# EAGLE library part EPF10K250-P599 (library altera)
EPF10K250 FLEX 10K family
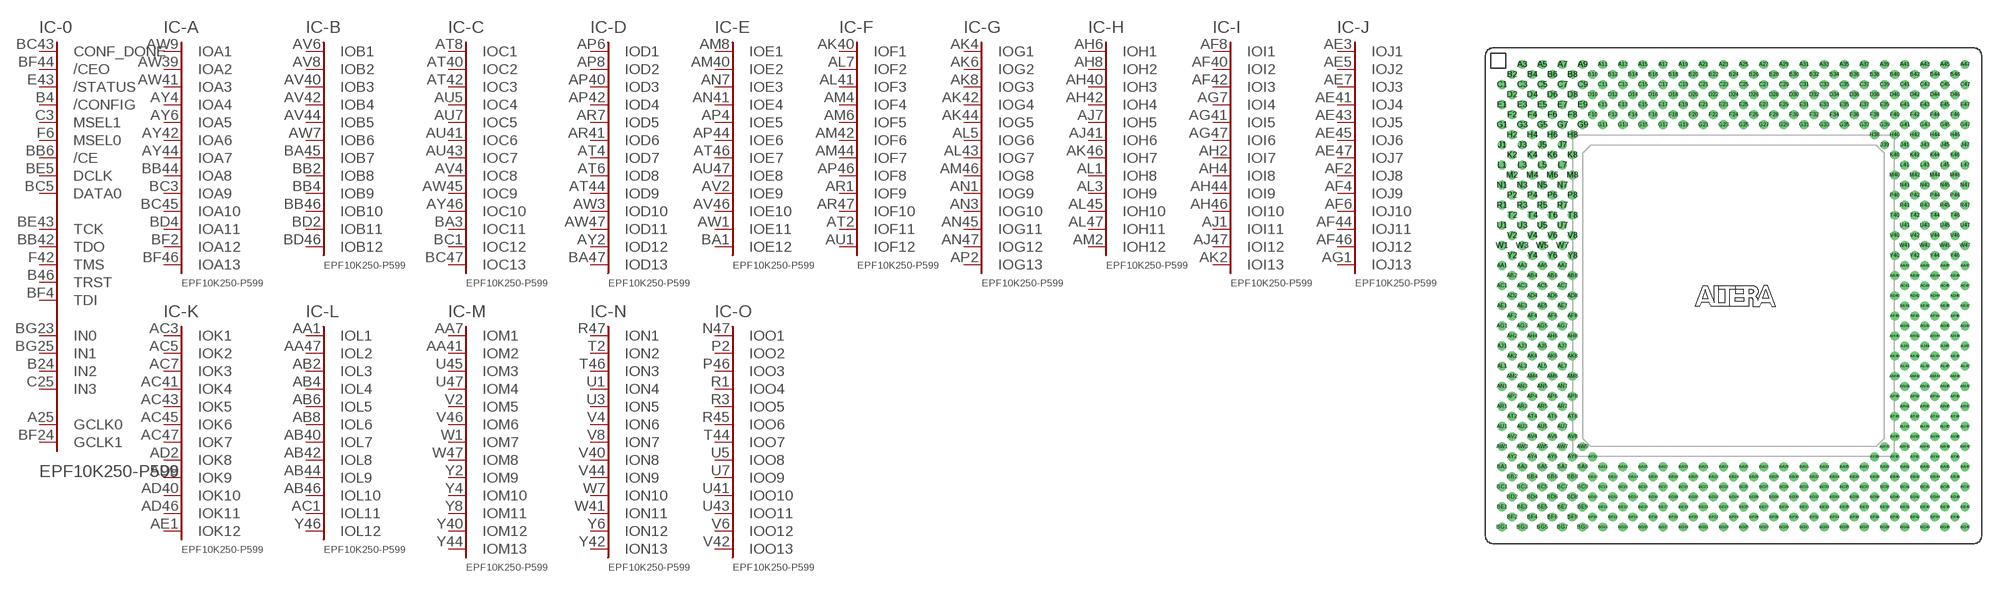
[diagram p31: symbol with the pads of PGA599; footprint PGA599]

Designator prefix IC; gates -0=K250_C -A=A13-250 -B=B12-250 -C=C13-250 -D=D13-250 -E=E12-250 -F=F12-250 -G=G13-250 -H=H12-250 -I=I13-250 -J=J13-250 -K=K12-250 -L=L12-250 -M=M13-250 -N=N13-250 -O=O13-250 -Q=Q14-250 -S=S13-250 -T=T14-250 -1=62-250 -2=122-250 -3=182-250 -4=242-250 -5=302-250 -6=361-250 -7=412-250 -8=471-250 -9=531-250 -10=583-250 -11=642-250 -12=702-250 -13=762-250 -P=P14-250 -R=R12-250 GI1=GNDINT GI2=GNDINT GI3=GNDINT GI4=GNDINT GI5=GNDINT GI6=GNDINT GI7=GNDINT GI8=GNDINT GI9=GNDINT GI10=GNDINT GI11=GNDINT GI12=GNDINT GI13=GNDINT GI14=GNDINT GI15=GNDINT GI16=GNDINT GI17=GNDINT GI18=GNDINT GI19=GNDINT GI20=GNDINT GI21=GNDINT GI22=GNDINT GI23=GNDINT GI24=GNDINT GI25=GNDINT GI26=GNDINT GO1=GNDIO GO2=GNDIO GO3=GNDIO GO4=GNDIO GO5=GNDIO GO6=GNDIO GO7=GNDIO GO8=GNDIO GO9=GNDIO GO10=GNDIO GO11=GNDIO GO12=GNDIO GO13=GNDIO GO14=GNDIO GO15=GNDIO GO16=GNDIO GO17=GNDIO GO18=GNDIO GO19=GNDIO GO20=GNDIO GO21=GNDIO GO22=GNDIO GO23=GNDIO GO24=GNDIO GO25=GNDIO GO26=GNDIO GO27=GNDIO GO28=GNDIO GO29=GNDIO GO30=GNDIO GO31=GNDIO V1=VCCINT V2=VCCINT V3=VCCINT V4=VCCINT V5=VCCINT V6=VCCINT V7=VCCINT V8=VCCINT V9=VCCINT V10=VCCINT V11=VCCINT V12=VCCINT V13=VCCINT V14=VCCINT V15=VCCINT V16=VCCINT V17=VCCINT V18=VCCINT V19=VCCINT V20=VCCINT V21=VCCINT V22=VCCINT V23=VCCINT V24=VCCINT V25=VCCINT V26=VCCINT VO1=VCCIO VO2=VCCIO VO3=VCCIO VO4=VCCIO VO5=VCCIO VO6=VCCIO VO7=VCCIO VO8=VCCIO VO9=VCCIO VO10=VCCIO VO11=VCCIO VO12=VCCIO VO13=VCCIO VO14=VCCIO VO15=VCCIO VO16=VCCIO VO17=VCCIO VO18=VCCIO VO19=VCCIO VO20=VCCIO VO21=VCCIO VO22=VCCIO VO23=VCCIO VO24=VCCIO VO25=VCCIO VO26=VCCIO VO27=VCCIO VO28=VCCIO VO29=VCCIO VO30=VCCIO VO31=VCCIO VO32=VCCIO

## EPF10K250-P599 (OC_FARNELL: unknown; OC_NEWARK: unknown)  [PGA599]
A3  V5:VCC  pwr
A5  -2:IO71
A7  -2:IO111
A9  -3:IO151
A11  -3:IO171
A13  -4:IO191
A15  -4:IO231
A17  -5:IO291
A19  -6:IO311
A21  -6:IO331
A23  -7:IO381
A25  -0:GCLK0  in
A27  -7:IO401
A29  -8:IO441
A31  -8:IO471
A33  -9:IO511
A35  -10:IO551
A37  -10:IO581
A39  -11:IO591
A41  -11:IO621
A43  -12:IO691
A45  V6:VCC  pwr
A47  GI7:GND  pwr
AA1  -L:IOL1
AA3  GI1:GND  pwr
AA5  VO1:VCCIO  pwr
AA7  -M:IOM1
AA41  -M:IOM2
AA43  VO2:VCCIO  pwr
AA45  GI2:GND  pwr
AA47  -L:IOL2
AB2  -L:IOL3
AB4  -L:IOL4
AB6  -L:IOL5
AB8  -L:IOL6
AB40  -L:IOL7
AB42  -L:IOL8
AB44  -L:IOL9
AB46  -L:IOL10
AC1  -L:IOL11
AC3  -K:IOK1
AC5  -K:IOK2
AC7  -K:IOK3
AC41  -K:IOK4
AC43  -K:IOK5
AC45  -K:IOK6
AC47  -K:IOK7
AD2  -K:IOK8
AD4  VO3:VCCIO  pwr
AD6  GO1:GNDIO  pwr
AD8  -K:IOK9
AD40  -K:IOK10
AD42  GO2:GNDIO  pwr
AD44  VO4:VCCIO  pwr
AD46  -K:IOK11
AE1  -K:IOK12
AE3  -J:IOJ1
AE5  -J:IOJ2
AE7  -J:IOJ3
AE41  -J:IOJ4
AE43  -J:IOJ5
AE45  -J:IOJ6
AE47  -J:IOJ7
AF2  -J:IOJ8
AF4  -J:IOJ9
AF6  -J:IOJ10
AF8  -I:IOI1
AF40  -I:IOI2
AF42  -I:IOI3
AF44  -J:IOJ11
AF46  -J:IOJ12
AG1  -J:IOJ13
AG3  GI3:GND  pwr
AG5  VO5:VCCIO  pwr
AG7  -I:IOI4
AG41  -I:IOI5
AG43  VO6:VCCIO  pwr
AG45  GI4:GND  pwr
AG47  -I:IOI6
AH2  -I:IOI7
AH4  -I:IOI8
AH6  -H:IOH1
AH8  -H:IOH2
AH40  -H:IOH3
AH42  -H:IOH4
AH44  -I:IOI9
AH46  -I:IOI10
AJ1  -I:IOI11
AJ3  V1:VCC  pwr
AJ5  GO3:GNDIO  pwr
AJ7  -H:IOH5
AJ41  -H:IOH6
AJ43  GO4:GNDIO  pwr
AJ45  V2:VCC  pwr
AJ47  -I:IOI12
AK2  -I:IOI13
AK4  -G:IOG1
AK6  -G:IOG2
AK8  -G:IOG3
AK40  -F:IOF1
AK42  -G:IOG4
AK44  -G:IOG5
AK46  -H:IOH7
AL1  -H:IOH8
AL3  -H:IOH9
AL5  -G:IOG6
AL7  -F:IOF2
AL41  -F:IOF3
AL43  -G:IOG7
AL45  -H:IOH10
AL47  -H:IOH11
AM2  -H:IOH12
AM4  -F:IOF4
AM6  -F:IOF5
AM8  -E:IOE1
AM40  -E:IOE2
AM42  -F:IOF6
AM44  -F:IOF7
AM46  -G:IOG8
AN1  -G:IOG9
AN3  -G:IOG10
AN5  VO7:VCCIO  pwr
AN7  -E:IOE3
AN41  -E:IOE4
AN43  VO8:VCCIO  pwr
AN45  -G:IOG11
AN47  -G:IOG12
AP2  -G:IOG13
AP4  -E:IOE5
AP6  -D:IOD1
AP8  -D:IOD2
AP40  -D:IOD3
AP42  -D:IOD4
AP44  -E:IOE6
AP46  -F:IOF8
AR1  -F:IOF9
AR3  GI5:GND  pwr
AR5  GO5:GNDIO  pwr
AR7  -D:IOD5
AR41  -D:IOD6
AR43  GO6:GNDIO  pwr
AR45  GI6:GND  pwr
AR47  -F:IOF10
AT2  -F:IOF11
AT4  -D:IOD7
AT6  -D:IOD8
AT8  -C:IOC1
AT40  -C:IOC2
AT42  -C:IOC3
AT44  -D:IOD9
AT46  -E:IOE7
AU1  -F:IOF12
AU3  V3:VCC  pwr
AU5  -C:IOC4
AU7  -C:IOC5
AU41  -C:IOC6
AU43  -C:IOC7
AU45  V4:VCC  pwr
AU47  -E:IOE8
AV2  -E:IOE9
AV4  -C:IOC8
AV6  -B:IOB1
AV8  -B:IOB2
AV40  -B:IOB3
AV42  -B:IOB4
AV44  -B:IOB5
AV46  -E:IOE10
AW1  -E:IOE11
AW3  -D:IOD10
AW5  VO9:VCCIO  pwr
AW7  -B:IOB6
AW9  -A:IOA1
AW39  -A:IOA2
AW41  -A:IOA3
AW43  VO10:VCCIO  pwr
AW45  -C:IOC9
AW47  -D:IOD11
AY2  -D:IOD12
AY4  -A:IOA4
AY6  -A:IOA5
AY8  GO7:GNDIO  pwr
AY10  -1:IO11
AY38  -13:IO761
AY40  GO8:GNDIO  pwr
AY42  -A:IOA6
AY44  -A:IOA7
AY46  -C:IOC10
B2  GI17:GND  pwr
B4  -0:/CONFIG  in
B6  -1:IO32
B8  -2:IO103
B10  -3:IO143
B12  -3:IO182
B14  -4:IO212
B16  -5:IO263
B18  -5:IO302
B20  -6:IO323
B22  -6:IO352
B24  -0:IN2  in
B26  -7:IO392
B28  -8:IO432
B30  -8:IO452
B32  -9:IO492
B34  -10:IO543
B36  -10:IO572
B38  -11:IO612
B40  -11:IO632
B42  -12:IO702
B44  -13:IO743
B46  -0:TRST
BA1  -E:IOE12
BA3  -C:IOC11
BA5  GO9:GNDIO  pwr
BA7  VO11:VCCIO  pwr
BA9  -1:IO21
BA11  -1:IO51
BA13  -2:IO101
BA15  -3:IO141
BA17  -4:IO211
BA19  -5:IO261
BA21  -6:IO332
BA23  -7:IO371
BA25  -7:IO402
BA27  -8:IO442
BA29  -9:IO512
BA31  -10:IO561
BA33  -11:IO622
BA35  -12:IO661
BA37  -13:IO721
BA39  -13:IO741
BA41  VO12:VCCIO  pwr
BA43  GO10:GNDIO  pwr
BA45  -B:IOB7
BA47  -D:IOD13
BB2  -B:IOB8
BB4  -B:IOB9
BB6  -0:/CE  in
BB8  -1:IO41
BB10  -2:IO81
BB12  -2:IO121
BB14  -3:IO161
BB16  -4:IO201
BB18  -5:IO251
BB20  -6:IO321
BB22  -6:IO361
BB24  GO11:GNDIO  pwr
BB26  -8:IO421
BB28  -8:IO461
BB30  -9:IO521
BB32  -10:IO582
BB34  -11:IO611
BB36  -12:IO651
BB38  -12:IO692
BB40  -13:IO731
BB42  -0:TDO
BB44  -A:IOA8
BB46  -B:IOB10
BC1  -C:IOC12
BC3  -A:IOA9
BC5  -0:DATA0  in
BC7  GO12:GNDIO  pwr
BC9  VO13:VCCIO  pwr
BC11  -2:IO91
BC13  GO13:GNDIO  pwr
BC15  VO14:VCCIO  pwr
BC17  -5:IO281
BC19  GO14:GNDIO  pwr
BC21  VO15:VCCIO  pwr
BC23  -7:IO382
BC25  -7:IO403
BC27  VO16:VCCIO  pwr
BC29  GO15:GNDIO  pwr
BC31  -9:IO501
BC33  VO17:VCCIO  pwr
BC35  GO16:GNDIO  pwr
BC37  -12:IO681
BC39  VO18:VCCIO  pwr
BC41  GO17:GNDIO  pwr
BC43  -0:CONF_DONE  in
BC45  -A:IOA10
BC47  -C:IOC13
BD2  -B:IOB11
BD4  -A:IOA11
BD6  -1:IO22
BD8  -1:IO42
BD10  -3:IO131
BD12  -3:IO172
BD14  -4:IO221
BD16  -4:IO241
BD18  -5:IO292
BD20  -6:IO341
BD22  -7:IO362
BD24  VO19:VCCIO  pwr
BD26  -7:IO411
BD28  -8:IO431
BD30  -9:IO481
BD32  -10:IO541
BD34  -10:IO552
BD36  -11:IO601
BD38  -11:IO641
BD40  -13:IO722
BD42  -13:IO751
BD44  GI8:GND  pwr
BD46  -B:IOB12
BE1  V7:VCC  pwr
BE3  GI9:GND  pwr
BE5  -0:DCLK  in
BE7  -1:IO61
BE9  -2:IO82
BE11  V8:VCC  pwr
BE13  GI10:GND  pwr
BE15  -4:IO222
BE17  -5:IO271
BE19  V9:VCC  pwr
BE21  GI11:GND  pwr
BE23  -7:IO383
BE25  -7:IO391
BE27  GI12:GND  pwr
BE29  V10:VCC  pwr
BE31  -9:IO502
BE33  -10:IO562
BE35  GI13:GND  pwr
BE37  V11:VCC  pwr
BE39  -12:IO682
BE41  -13:IO711
BE43  -0:TCK
BE45  GI14:GND  pwr
BE47  V12:VCC  pwr
BF2  -A:IOA12
BF4  -0:TDI
BF6  -1:IO31
BF8  -2:IO102
BF10  -3:IO142
BF12  -3:IO181
BF14  -4:IO202
BF16  -5:IO262
BF18  -5:IO301
BF20  -6:IO322
BF22  -6:IO351
BF24  -0:GCLK1  in
BF26  -8:IO422
BF28  -8:IO451
BF30  -9:IO482
BF32  -9:IO522
BF34  -10:IO571
BF36  -11:IO592
BF38  -11:IO631
BF40  -12:IO671
BF42  -13:IO742
BF44  -0:/CEO  in
BF46  -A:IOA13
BG1  GI15:GND  pwr
BG3  V13:VCC  pwr
BG5  -2:IO72
BG7  -2:IO112
BG9  -3:IO152
BG11  -3:IO162
BG13  -4:IO192
BG15  -4:IO232
BG17  -5:IO282
BG19  -6:IO312
BG21  -6:IO342
BG23  -0:IN0  in
BG25  -0:IN1  in
BG27  -8:IO443
BG29  -8:IO462
BG31  -9:IO491
BG33  -10:IO542
BG35  -10:IO583
BG37  -11:IO602
BG39  -11:IO623
BG41  -12:IO662
BG43  -12:IO701
BG45  V14:VCC  pwr
BG47  GI16:GND  pwr
C1  V15:VCC  pwr
C3  -0:MSEL1  in
C5  -1:IO23
C7  -1:IO62
C9  -2:IO92
C11  V16:VCC  pwr
C13  GI18:GND  pwr
C15  -4:IO223
C17  -5:IO272
C19  V17:VCC  pwr
C21  GI19:GND  pwr
C23  -7:IO372
C25  -0:IN3  in
C27  GI20:GND  pwr
C29  V18:VCC  pwr
C31  -9:IO483
C33  -9:IO523
C35  GI21:GND  pwr
C37  V19:VCC  pwr
C39  -12:IO672
C41  -13:IO732
C43  -13:IO752
C45  GI22:GND  pwr
C47  V20:VCC  pwr
D2  -T:IOT1
D4  GI23:GND  pwr
D6  -1:IO43
D8  -1:IO52
D10  -3:IO132
D12  -3:IO173
D14  -4:IO233
D16  -4:IO242
D18  -5:IO293
D20  -6:IO343
D22  -6:IO353
D24  VO20:VCCIO  pwr
D26  -8:IO423
D28  -8:IO433
D30  -9:IO493
D32  -9:IO531
D34  -10:IO553
D36  -11:IO603
D38  -11:IO642
D40  -12:IO683
D42  -13:IO723
D44  -T:IOT2
D46  -T:IOT3
E1  -T:IOT4
E3  -T:IOT5
E5  V21:VCC  pwr
E7  GO18:GNDIO  pwr
E9  VO21:VCCIO  pwr
E11  -2:IO93
E13  GO19:GNDIO  pwr
E15  VO22:VCCIO  pwr
E17  -5:IO283
E19  GO20:GNDIO  pwr
E21  VO23:VCCIO  pwr
E23  -7:IO373
E25  -7:IO393
E27  VO24:VCCIO  pwr
E29  GO21:GNDIO  pwr
E31  -9:IO503
E33  VO25:VCCIO  pwr
E35  GO22:GNDIO  pwr
E37  -12:IO652
E39  VO26:VCCIO  pwr
E41  GO23:GNDIO  pwr
E43  -0:/STATUS  in
E45  -T:IOT6
E47  -T:IOT7
F2  -S:IOS1
F4  -T:IOT8
F6  -0:MSEL0  in
F8  -1:IO33
F10  -2:IO83
F12  -2:IO122
F14  -3:IO163
F16  -4:IO203
F18  -5:IO252
F20  -6:IO313
F22  -7:IO363
F24  GO24:GNDIO  pwr
F26  -7:IO412
F28  -8:IO463
F30  -10:IO532
F32  -10:IO573
F34  -11:IO613
F36  -12:IO673
F38  -12:IO693
F40  -13:IO733
F42  -0:TMS
F44  -S:IOS2
F46  -S:IOS3
G1  -R:IOR1
G3  -S:IOS4
G5  GO25:GNDIO  pwr
G7  VO27:VCCIO  pwr
G9  -1:IO12
G11  -1:IO53
G13  -2:IO113
G15  -3:IO153
G17  -4:IO213
G19  -5:IO273
G21  -6:IO333
G23  GI24:GND  pwr
G25  V22:VCC  pwr
G27  -8:IO453
G29  -9:IO513
G31  -10:IO563
G33  -11:IO633
G35  -12:IO663
G37  -13:IO712
G39  -13:IO753
G41  VO28:VCCIO  pwr
G43  GO26:GNDIO  pwr
G45  -S:IOS5
G47  -R:IOR2
H2  -R:IOR3
H4  -S:IOS6
H6  -T:IOT9
H8  -T:IOT10
H38  -13:IO762
H40  GO27:GNDIO  pwr
H42  -T:IOT11
H44  -R:IOR4
H46  -Q:IOQ1
J1  -Q:IOQ2
J3  -Q:IOQ3
J5  VO29:VCCIO  pwr
J7  -T:IOT12
J39  -T:IOT13
J41  -T:IOT14
J43  VO30:VCCIO  pwr
J45  -Q:IOQ4
J47  -Q:IOQ5
K2  -Q:IOQ6
K4  -S:IOS7
K6  -S:IOS8
K8  -S:IOS9
K40  -S:IOS10
K42  -S:IOS11
K44  -S:IOS12
K46  -P:IOP1
L1  -P:IOP2
L3  V23:VCC  pwr
L5  -R:IOR5
L7  -S:IOS13
L41  -R:IOR6
L43  -R:IOR7
L45  V24:VCC  pwr
L47  -P:IOP3
M2  -P:IOP4
M4  -R:IOR8
M6  -R:IOR9
M8  -R:IOR10
M40  -R:IOR11
M42  -R:IOR12
M44  -Q:IOQ7
M46  -P:IOP5
N1  -P:IOP6
N3  GI25:GND  pwr
N5  GO28:GNDIO  pwr
N7  -Q:IOQ8
N41  -Q:IOQ9
N43  GO29:GNDIO  pwr
N45  GI26:GND  pwr
N47  -O:IOO1
P2  -O:IOO2
P4  -Q:IOQ10
P6  -Q:IOQ11
P8  -Q:IOQ12
P40  -P:IOP7
P42  -Q:IOQ13
P44  -Q:IOQ14
P46  -O:IOO3
R1  -O:IOO4
R3  -O:IOO5
R5  VO31:VCCIO  pwr
R7  -P:IOP8
R41  -P:IOP9
R43  VO32:VCCIO  pwr
R45  -O:IOO6
R47  -N:ION1
T2  -N:ION2
T4  -P:IOP10
T6  -P:IOP11
T8  -P:IOP12
T40  -P:IOP13
T42  -P:IOP14
T44  -O:IOO7
T46  -N:ION3
U1  -N:ION4
U3  -N:ION5
U5  -O:IOO8
U7  -O:IOO9
U41  -O:IOO10
U43  -O:IOO11
U45  -M:IOM3
U47  -M:IOM4
V2  -M:IOM5
V4  -N:ION6
V6  -O:IOO12
V8  -N:ION7
V40  -N:ION8
V42  -O:IOO13
V44  -N:ION9
V46  -M:IOM6
W1  -M:IOM7
W3  V25:VCC  pwr
W5  GO30:GNDIO  pwr
W7  -N:ION10
W41  -N:ION11
W43  GO31:GNDIO  pwr
W45  V26:VCC  pwr
W47  -M:IOM8
Y2  -M:IOM9
Y4  -M:IOM10
Y6  -N:ION12
Y8  -M:IOM11
Y40  -M:IOM12
Y42  -N:ION13
Y44  -M:IOM13
Y46  -L:IOL12

## Footprint PGA599 (pad centres in mm)
Pin Grid Array
drill 0.61 pad 1.016 round: A3 -26.67,29.21; A5 -24.13,29.21; A7 -21.59,29.21; A9 -19.05,29.21; A11 -16.51,29.21; A13 -13.97,29.21; A15 -11.43,29.21; A17 -8.89,29.21; A19 -6.35,29.21; A21 -3.81,29.21; A23 -1.27,29.21; A25 1.27,29.21; A27 3.81,29.21; A29 6.35,29.21; A31 8.89,29.21; A33 11.43,29.21; A35 13.97,29.21; A37 16.51,29.21; A39 19.05,29.21; A41 21.59,29.21; A43 24.13,29.21; A45 26.67,29.21; A47 29.21,29.21; AA1 -29.21,3.81; AA3 -26.67,3.81; AA5 -24.13,3.81; AA7 -21.59,3.81; AA41 21.59,3.81; AA43 24.13,3.81; AA45 26.67,3.81; AA47 29.21,3.81; AB2 -27.94,2.54; AB4 -25.4,2.54; AB6 -22.86,2.54; AB8 -20.32,2.54; AB40 20.32,2.54; AB42 22.86,2.54; AB44 25.4,2.54; AB46 27.94,2.54; AC1 -29.21,1.27; AC3 -26.67,1.27; AC5 -24.13,1.27; AC7 -21.59,1.27; AC41 21.59,1.27; AC43 24.13,1.27; AC45 26.67,1.27; AC47 29.21,1.27; AD2 -27.94,0; AD4 -25.4,0; AD6 -22.86,0; AD8 -20.32,0; AD40 20.32,0; AD42 22.86,0; AD44 25.4,0; AD46 27.94,0; AE1 -29.21,-1.27; AE3 -26.67,-1.27; AE5 -24.13,-1.27; AE7 -21.59,-1.27; AE41 21.59,-1.27; AE43 24.13,-1.27; AE45 26.67,-1.27; AE47 29.21,-1.27; AF2 -27.94,-2.54; AF4 -25.4,-2.54; AF6 -22.86,-2.54; AF8 -20.32,-2.54; AF40 20.32,-2.54; AF42 22.86,-2.54; AF44 25.4,-2.54; AF46 27.94,-2.54; AG1 -29.21,-3.81; AG3 -26.67,-3.81; AG5 -24.13,-3.81; AG7 -21.59,-3.81; AG41 21.59,-3.81; AG43 24.13,-3.81; AG45 26.67,-3.81; AG47 29.21,-3.81; AH2 -27.94,-5.08; AH4 -25.4,-5.08; AH6 -22.86,-5.08; AH8 -20.32,-5.08; AH40 20.32,-5.08; AH42 22.86,-5.08; AH44 25.4,-5.08; AH46 27.94,-5.08; AJ1 -29.21,-6.35; AJ3 -26.67,-6.35; AJ5 -24.13,-6.35; AJ7 -21.59,-6.35; AJ41 21.59,-6.35; AJ43 24.13,-6.35; AJ45 26.67,-6.35; AJ47 29.21,-6.35; AK2 -27.94,-7.62; AK4 -25.4,-7.62; AK6 -22.86,-7.62; AK8 -20.32,-7.62; AK40 20.32,-7.62; AK42 22.86,-7.62; AK44 25.4,-7.62; AK46 27.94,-7.62; AL1 -29.21,-8.89; AL3 -26.67,-8.89; AL5 -24.13,-8.89; AL7 -21.59,-8.89; AL41 21.59,-8.89; AL43 24.13,-8.89; AL45 26.67,-8.89; AL47 29.21,-8.89; AM2 -27.94,-10.16; AM4 -25.4,-10.16; AM6 -22.86,-10.16; AM8 -20.32,-10.16; AM40 20.32,-10.16; AM42 22.86,-10.16; AM44 25.4,-10.16; AM46 27.94,-10.16; AN1 -29.21,-11.43; AN3 -26.67,-11.43; AN5 -24.13,-11.43; AN7 -21.59,-11.43; AN41 21.59,-11.43; AN43 24.13,-11.43; AN45 26.67,-11.43; AN47 29.21,-11.43; AP2 -27.94,-12.7; AP4 -25.4,-12.7; AP6 -22.86,-12.7; AP8 -20.32,-12.7; AP40 20.32,-12.7; AP42 22.86,-12.7; AP44 25.4,-12.7; AP46 27.94,-12.7; AR1 -29.21,-13.97; AR3 -26.67,-13.97; AR5 -24.13,-13.97; AR7 -21.59,-13.97; AR41 21.59,-13.97; AR43 24.13,-13.97; AR45 26.67,-13.97; AR47 29.21,-13.97; AT2 -27.94,-15.24; AT4 -25.4,-15.24; AT6 -22.86,-15.24; AT8 -20.32,-15.24; AT40 20.32,-15.24; AT42 22.86,-15.24; AT44 25.4,-15.24; AT46 27.94,-15.24; AU1 -29.21,-16.51; AU3 -26.67,-16.51; AU5 -24.13,-16.51; AU7 -21.59,-16.51; AU41 21.59,-16.51; AU43 24.13,-16.51; AU45 26.67,-16.51; AU47 29.21,-16.51; AV2 -27.94,-17.78; AV4 -25.4,-17.78; AV6 -22.86,-17.78; AV8 -20.32,-17.78; AV40 20.32,-17.78; AV42 22.86,-17.78; AV44 25.4,-17.78; AV46 27.94,-17.78; AW1 -29.21,-19.05; AW3 -26.67,-19.05; AW5 -24.13,-19.05; AW7 -21.59,-19.05; AW9 -19.05,-19.05; AW39 19.05,-19.05; AW41 21.59,-19.05; AW43 24.13,-19.05; AW45 26.67,-19.05; AW47 29.21,-19.05; AY2 -27.94,-20.32; AY4 -25.4,-20.32; AY6 -22.86,-20.32; AY8 -20.32,-20.32; AY10 -17.78,-20.32; AY38 17.78,-20.32; AY40 20.32,-20.32; AY42 22.86,-20.32; AY44 25.4,-20.32; AY46 27.94,-20.32; B2 -27.94,27.94; B4 -25.4,27.94; B6 -22.86,27.94; B8 -20.32,27.94; B10 -17.78,27.94; B12 -15.24,27.94; B14 -12.7,27.94; B16 -10.16,27.94; B18 -7.62,27.94; B20 -5.08,27.94; B22 -2.54,27.94; B24 0,27.94; B26 2.54,27.94; B28 5.08,27.94; B30 7.62,27.94; B32 10.16,27.94; B34 12.7,27.94; B36 15.24,27.94; B38 17.78,27.94; B40 20.32,27.94; B42 22.86,27.94; B44 25.4,27.94; B46 27.94,27.94; BA1 -29.21,-21.59; BA3 -26.67,-21.59; BA5 -24.13,-21.59; BA7 -21.59,-21.59; BA9 -19.05,-21.59; BA11 -16.51,-21.59; BA13 -13.97,-21.59; BA15 -11.43,-21.59; BA17 -8.89,-21.59; BA19 -6.35,-21.59; BA21 -3.81,-21.59; BA23 -1.27,-21.59; BA25 1.27,-21.59; BA27 3.81,-21.59; BA29 6.35,-21.59; BA31 8.89,-21.59; BA33 11.43,-21.59; BA35 13.97,-21.59; BA37 16.51,-21.59; BA39 19.05,-21.59; BA41 21.59,-21.59; BA43 24.13,-21.59; BA45 26.67,-21.59; BA47 29.21,-21.59; BB2 -27.94,-22.86; BB4 -25.4,-22.86; BB6 -22.86,-22.86; BB8 -20.32,-22.86; BB10 -17.78,-22.86; BB12 -15.24,-22.86; BB14 -12.7,-22.86; BB16 -10.16,-22.86; BB18 -7.62,-22.86; BB20 -5.08,-22.86; BB22 -2.54,-22.86; BB24 0,-22.86; BB26 2.54,-22.86; BB28 5.08,-22.86; BB30 7.62,-22.86; BB32 10.16,-22.86; BB34 12.7,-22.86; BB36 15.24,-22.86; BB38 17.78,-22.86; BB40 20.32,-22.86; BB42 22.86,-22.86; BB44 25.4,-22.86; BB46 27.94,-22.86; BC1 -29.21,-24.13; BC3 -26.67,-24.13; BC5 -24.13,-24.13; BC7 -21.59,-24.13; BC9 -19.05,-24.13; BC11 -16.51,-24.13; BC13 -13.97,-24.13; BC15 -11.43,-24.13; BC17 -8.89,-24.13; BC19 -6.35,-24.13; BC21 -3.81,-24.13; BC23 -1.27,-24.13; BC25 1.27,-24.13; BC27 3.81,-24.13; BC29 6.35,-24.13; BC31 8.89,-24.13; BC33 11.43,-24.13; BC35 13.97,-24.13; BC37 16.51,-24.13; BC39 19.05,-24.13; BC41 21.59,-24.13; BC43 24.13,-24.13; BC45 26.67,-24.13; BC47 29.21,-24.13; BD2 -27.94,-25.4; BD4 -25.4,-25.4; BD6 -22.86,-25.4; BD8 -20.32,-25.4; BD10 -17.78,-25.4; BD12 -15.24,-25.4; BD14 -12.7,-25.4; BD16 -10.16,-25.4; BD18 -7.62,-25.4; BD20 -5.08,-25.4; BD22 -2.54,-25.4; BD24 0,-25.4; BD26 2.54,-25.4; BD28 5.08,-25.4; BD30 7.62,-25.4; BD32 10.16,-25.4; BD34 12.7,-25.4; BD36 15.24,-25.4; BD38 17.78,-25.4; BD40 20.32,-25.4; BD42 22.86,-25.4; BD44 25.4,-25.4; BD46 27.94,-25.4; BE1 -29.21,-26.67; BE3 -26.67,-26.67; BE5 -24.13,-26.67; BE7 -21.59,-26.67; BE9 -19.05,-26.67; BE11 -16.51,-26.67; BE13 -13.97,-26.67; BE15 -11.43,-26.67; BE17 -8.89,-26.67; BE19 -6.35,-26.67; BE21 -3.81,-26.67; BE23 -1.27,-26.67; BE25 1.27,-26.67; BE27 3.81,-26.67; BE29 6.35,-26.67; BE31 8.89,-26.67; BE33 11.43,-26.67; BE35 13.97,-26.67; BE37 16.51,-26.67; BE39 19.05,-26.67; BE41 21.59,-26.67; BE43 24.13,-26.67; BE45 26.67,-26.67; BE47 29.21,-26.67; BF2 -27.94,-27.94; BF4 -25.4,-27.94; BF6 -22.86,-27.94; BF8 -20.32,-27.94; BF10 -17.78,-27.94; BF12 -15.24,-27.94; BF14 -12.7,-27.94; BF16 -10.16,-27.94; BF18 -7.62,-27.94; BF20 -5.08,-27.94; BF22 -2.54,-27.94; BF24 0,-27.94; BF26 2.54,-27.94; BF28 5.08,-27.94; BF30 7.62,-27.94; BF32 10.16,-27.94; BF34 12.7,-27.94; BF36 15.24,-27.94; BF38 17.78,-27.94; BF40 20.32,-27.94; BF42 22.86,-27.94; BF44 25.4,-27.94; BF46 27.94,-27.94; BG1 -29.21,-29.21; BG3 -26.67,-29.21; BG5 -24.13,-29.21; BG7 -21.59,-29.21; BG9 -19.05,-29.21; BG11 -16.51,-29.21; BG13 -13.97,-29.21; BG15 -11.43,-29.21; BG17 -8.89,-29.21; BG19 -6.35,-29.21; BG21 -3.81,-29.21; BG23 -1.27,-29.21; BG25 1.27,-29.21; BG27 3.81,-29.21; BG29 6.35,-29.21; BG31 8.89,-29.21; BG33 11.43,-29.21; BG35 13.97,-29.21; BG37 16.51,-29.21; BG39 19.05,-29.21; BG41 21.59,-29.21; BG43 24.13,-29.21; BG45 26.67,-29.21; BG47 29.21,-29.21; C1 -29.21,26.67; C3 -26.67,26.67; C5 -24.13,26.67; C7 -21.59,26.67; C9 -19.05,26.67; C11 -16.51,26.67; C13 -13.97,26.67; C15 -11.43,26.67; C17 -8.89,26.67; C19 -6.35,26.67; C21 -3.81,26.67; C23 -1.27,26.67; C25 1.27,26.67; C27 3.81,26.67; C29 6.35,26.67; C31 8.89,26.67; C33 11.43,26.67; C35 13.97,26.67; C37 16.51,26.67; C39 19.05,26.67; C41 21.59,26.67; C43 24.13,26.67; C45 26.67,26.67; C47 29.21,26.67; D2 -27.94,25.4; D4 -25.4,25.4; D6 -22.86,25.4; D8 -20.32,25.4; D10 -17.78,25.4; D12 -15.24,25.4; D14 -12.7,25.4; D16 -10.16,25.4; D18 -7.62,25.4; D20 -5.08,25.4; D22 -2.54,25.4; D24 0,25.4; D26 2.54,25.4; D28 5.08,25.4; D30 7.62,25.4; D32 10.16,25.4; D34 12.7,25.4; D36 15.24,25.4; D38 17.78,25.4; D40 20.32,25.4; D42 22.86,25.4; D44 25.4,25.4; D46 27.94,25.4; E1 -29.21,24.13; E3 -26.67,24.13; E5 -24.13,24.13; E7 -21.59,24.13; E9 -19.05,24.13; E11 -16.51,24.13; E13 -13.97,24.13; E15 -11.43,24.13; E17 -8.89,24.13; E19 -6.35,24.13; E21 -3.81,24.13; E23 -1.27,24.13; E25 1.27,24.13; E27 3.81,24.13; E29 6.35,24.13; E31 8.89,24.13; E33 11.43,24.13; E35 13.97,24.13; E37 16.51,24.13; E39 19.05,24.13; E41 21.59,24.13; E43 24.13,24.13; E45 26.67,24.13; E47 29.21,24.13; F2 -27.94,22.86; F4 -25.4,22.86; F6 -22.86,22.86; F8 -20.32,22.86; F10 -17.78,22.86; F12 -15.24,22.86; F14 -12.7,22.86; F16 -10.16,22.86; F18 -7.62,22.86; F20 -5.08,22.86; F22 -2.54,22.86; F24 0,22.86; F26 2.54,22.86; F28 5.08,22.86; F30 7.62,22.86; F32 10.16,22.86; F34 12.7,22.86; F36 15.24,22.86; F38 17.78,22.86; F40 20.32,22.86; F42 22.86,22.86; F44 25.4,22.86; F46 27.94,22.86; G1 -29.21,21.59; G3 -26.67,21.59; G5 -24.13,21.59; G7 -21.59,21.59; G9 -19.05,21.59; G11 -16.51,21.59; G13 -13.97,21.59; G15 -11.43,21.59; G17 -8.89,21.59; G19 -6.35,21.59; G21 -3.81,21.59; G23 -1.27,21.59; G25 1.27,21.59; G27 3.81,21.59; G29 6.35,21.59; G31 8.89,21.59; G33 11.43,21.59; G35 13.97,21.59; G37 16.51,21.59; G39 19.05,21.59; G41 21.59,21.59; G43 24.13,21.59; G45 26.67,21.59; G47 29.21,21.59; H2 -27.94,20.32; H4 -25.4,20.32; H6 -22.86,20.32; H8 -20.32,20.32; H38 17.78,20.32; H40 20.32,20.32; H42 22.86,20.32; H44 25.4,20.32; H46 27.94,20.32; J1 -29.21,19.05; J3 -26.67,19.05; J5 -24.13,19.05; J7 -21.59,19.05; J39 19.05,19.05; J41 21.59,19.05; J43 24.13,19.05; J45 26.67,19.05; J47 29.21,19.05; K2 -27.94,17.78; K4 -25.4,17.78; K6 -22.86,17.78; K8 -20.32,17.78; K40 20.32,17.78; K42 22.86,17.78; K44 25.4,17.78; K46 27.94,17.78; L1 -29.21,16.51; L3 -26.67,16.51; L5 -24.13,16.51; L7 -21.59,16.51; L41 21.59,16.51; L43 24.13,16.51; L45 26.67,16.51; L47 29.21,16.51; M2 -27.94,15.24; M4 -25.4,15.24; M6 -22.86,15.24; M8 -20.32,15.24; M40 20.32,15.24; M42 22.86,15.24; M44 25.4,15.24; M46 27.94,15.24; N1 -29.21,13.97; N3 -26.67,13.97; N5 -24.13,13.97; N7 -21.59,13.97; N41 21.59,13.97; N43 24.13,13.97; N45 26.67,13.97; N47 29.21,13.97; P2 -27.94,12.7; P4 -25.4,12.7; P6 -22.86,12.7; P8 -20.32,12.7; P40 20.32,12.7; P42 22.86,12.7; P44 25.4,12.7; P46 27.94,12.7; R1 -29.21,11.43; R3 -26.67,11.43; R5 -24.13,11.43; R7 -21.59,11.43; R41 21.59,11.43; R43 24.13,11.43; R45 26.67,11.43; R47 29.21,11.43; T2 -27.94,10.16; T4 -25.4,10.16; T6 -22.86,10.16; T8 -20.32,10.16; T40 20.32,10.16; T42 22.86,10.16; T44 25.4,10.16; T46 27.94,10.16; U1 -29.21,8.89; U3 -26.67,8.89; U5 -24.13,8.89; U7 -21.59,8.89; U41 21.59,8.89; U43 24.13,8.89; U45 26.67,8.89; U47 29.21,8.89; V2 -27.94,7.62; V4 -25.4,7.62; V6 -22.86,7.62; V8 -20.32,7.62; V40 20.32,7.62; V42 22.86,7.62; V44 25.4,7.62; V46 27.94,7.62; W1 -29.21,6.35; W3 -26.67,6.35; W5 -24.13,6.35; W7 -21.59,6.35; W41 21.59,6.35; W43 24.13,6.35; W45 26.67,6.35; W47 29.21,6.35; Y2 -27.94,5.08; Y4 -25.4,5.08; Y6 -22.86,5.08; Y8 -20.32,5.08; Y40 20.32,5.08; Y42 22.86,5.08; Y44 25.4,5.08; Y46 27.94,5.08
